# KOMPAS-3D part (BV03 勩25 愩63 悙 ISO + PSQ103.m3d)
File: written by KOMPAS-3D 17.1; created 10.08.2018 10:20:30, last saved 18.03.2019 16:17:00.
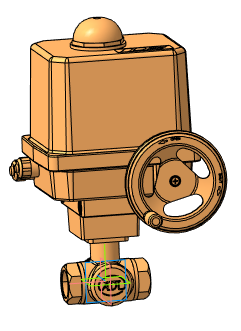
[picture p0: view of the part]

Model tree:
1. Операция без истории:2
